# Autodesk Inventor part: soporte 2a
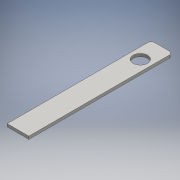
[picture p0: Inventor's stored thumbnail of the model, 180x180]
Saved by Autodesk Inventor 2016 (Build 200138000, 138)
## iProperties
Created: 2016-06
Part Number: soporte 2a
Material: Genérico
Document SubType Name: Modeling
Designer: adm
Density: 1 g/cm^3
Appearance: Valor por defecto
Author: adm
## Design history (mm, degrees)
sketch "Boceto1"
  geometry: L1 (-15, -100)-(15, -100); L2 (15, -100)-(15, 100); L3 (15, 100)-(-15, 100); L4 (-15, 100)-(-15, -100); L5 (-15, -100)-(15, 100); L6 (15, -100)-(-15, 100); 1 further point
  constraints: 12 end point, 2 midpoint, 2 parallel, 1 horizontal, 1 perpendicular
  dimensions: "d0" = 30 distance of L2.end L3.end; "d1" = 200 distance of L3.end L1.start
extrude "Extrusión1" new body sketch "Boceto1" distance "d2" = 4; taper "d3" = 0 deg
fillet "Empalme1" dims "d4" = 5
sketch "Boceto3"
  geometry: L1 (10, 100)-(-10, 100) reference; C1 r 10 at (0, 70); 2 further points
  constraints: 1 centre point, 1 coincident
  dimensions: "d12" = 30 distance from line of point (0, 70) L1; "d13" = 20 diameter of C1
extrude "Extrusión3" cut sketch "Boceto3" distance "d14" = 10; taper "d15" = 0 deg
node "Sólido1"
